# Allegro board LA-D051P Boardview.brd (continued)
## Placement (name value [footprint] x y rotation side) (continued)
PC111  4.7U_0603_6.3V6M  [C_0603]  65.27 16.56 90 bottom
PC112  680P_0603_50V7K  [C_0603]  68.26 18.09 180 bottom
PC113  1000P_0402_25V8J  [C_0402]  61.46 18.53 90 bottom
PC114  0.1U_0603_25V7K  [C_0603]  64.79 21.2 90 bottom
PC115  0.1U_0402_25V6  [C_0402]  58.22 25.32 90 top
PC116  2200P_0402_50V7K  [C_0402]  58.22 25.32 90 bottom
PC117  10U_0805_25V6K  [C_0805]  59.56 25.05 90 bottom
PC118  10U_0805_25V6K  [C_0805]  59.56 25.05 90 top
PC119  4.7U_0603_6.3V6M  [C_0603]  66.03 27.36 90 bottom
PC120  22U_0805_6.3V6M  [C_0805]  74.61 27.49 90 bottom
PC121  22U_0805_6.3V6M  [C_0805]  76.32 27.49 90 bottom
PC122  22U_0805_6.3V6M  [C_0805]  72.83 28.19 90 bottom
PC123  22U_0805_6.3V6M  [C_0805]  78.03 27.49 90 bottom
PC124  22U_0805_6.3V6M  [C_0805]  78.07 25.2 0 bottom
PC125  680P_0603_50V7K  [C_0603]  68.64 30.28 180 bottom
PC126  4.7U_0603_6.3V6M  [C_0603]  64.83 30.28 0 bottom
PC127  1000P_0402_25V8J  [C_0402]  61.72 30.28 90 bottom
PC128  4.7U_0402_6.3V6M  [C_0402]  61.78 30.2 90 top
PC200  0.1U_0603_25V7K  [C_0603]  89.78 14.91 180 bottom
PC201  2200P_0402_50V7K  [C_0402]  88.65 23.93 180 bottom
PC202  0.1U_0402_10V7K  [C_0402]  83.81 14.15 0 top
PC203  0.1U_0402_10V7K  [C_0402]  83.81 13.14 0 top
PC204  1U_0603_10V6K  [C_0603]  84.97 18.27 270 bottom
PC205  10U_0805_6.3V6K  [C_0805]  87.08 9.45 180 bottom
PC206  10U_0805_25V6K  [C_0805]  91.28 19.87 0 bottom
PC207  680P_0402_50V7K  [C_0402]  92.7 15.35 90 top
PC208  0.1U_0402_25V6  [C_0402]  88.65 23.04 180 bottom
PC209  1U_0603_10V6K  [C_0603]  81.31 16.89 90 bottom
PC210  0.033U_0402_16V7K  [C_0402]  84.26 10.42 270 bottom
PC211  10U_0805_6.3V6K  [C_0805]  87.08 7.67 180 bottom
PC212  10U_0805_25V6K  [C_0805]  88.73 21.71 180 bottom
PC213  .1U_0402_16V7K  [C_0402]  83.37 10.42 270 bottom
PC214  220P_0402_25V8J  [C_0402]  81.97 10.42 270 bottom
PC215  22U_0603_6.3V6M  [C_0603]  97.78 19.82 180 bottom
PC216  22U_0603_6.3V6M  [C_0603]  97.78 21.02 180 bottom
PC217  22U_0603_6.3V6M  [C_0603]  97.78 22.21 180 bottom
PC218  22U_0603_6.3V6M  [C_0603]  97.78 23.4 180 bottom
PC219  22U_0603_6.3V6M  [C_0603]  97.78 24.6 180 bottom
PC220  22U_0603_6.3V6M  [C_0603]  97.78 25.79 180 bottom
PC301  0.1U_0402_25V6  [C_0402]  174.24 50.93 270 bottom
PC302  680P_0603_50V7K  [C_0603]  174.24 46.66 90 bottom
PC303  2200P_0402_50V7K  [C_0402]  173.35 50.92 270 bottom
PC304  0.1U_0603_25V7K  [C_0603]  182.56 53.65 180 bottom
PC305  10U_0805_25V6K  [C_0805]  175.57 51.01 270 top
PC306  10U_0805_25V6K  [C_0805]  175.57 51.01 270 bottom
PC307  330P_0402_50V7K  [C_0402]  183.54 49.09 180 bottom
PC308  47U_0805_6.3V6M  [C_0805]  181.92 38.95 90 top
PC309  47U_0805_6.3V6M  [C_0805]  180.02 38.95 90 top
PC310  22U_0805_6.3VAM  [C_0805]  176.46 38.95 90 top
PC311  22U_0805_6.3VAM  [C_0805]  178.24 38.95 90 top
PC312  4.7U_0603_6.3V6K  [C_0603]  179.23 52.75 90 bottom
PC313  4.7U_0603_6.3V6K  [C_0603]  181.15 51.15 0 bottom
PC405  0.1U_0402_25V6  [C_0402]  182.23 46.41 0 bottom
PC501  22U_0603_6.3V6M  [C_0603]  82.79 31.75 180 bottom
PC502  22U_0603_6.3V6M  [C_0603]  87.5 26.78 270 bottom
PC503  68P_0402_50V8J  [C_0402]  81.79 26.06 270 bottom
PC504  22U_0603_6.3V6M  [C_0603]  82.8 30.53 180 bottom
PC505  0.1U_0402_16V7K  [C_0402]  82.67 28.26 270 bottom
PC506  680P_0402_50V7K  [C_0402]  87.69 28.69 270 bottom
PC601  680P_0402_50V7K  [C_0402]  87.81 118.15 90 top
PC602  0.1U_0402_25V6  [C_0402]  97.1 114.86 180 top
PC603  1U_0603_10V6K  [C_0603]  94.24 115.41 0 bottom
PC604  0.22U_0603_25V7K  [C_0603]  94.19 116.66 0 bottom
PC605  47P_0402_50V8J~D  [C_0402]  97.1 111.31 180 bottom
PC606  33U_25V_M  [C_VSS330M1ETR-0604]  73.37 117.21 0 bottom
PC608  10U_0805_25V6K  [C_0805]  146.55 118.32 270 top
PC611  0.22U_0603_16V7K  [C_0603]  148.9 115.24 270 top
PC612  10U_0805_25V6K  [C_0805]  146.55 118.32 270 bottom
PC613  330P_0402_50V8J  [C_0402]  91.03 111.79 270 top
PC614  2200P_0402_50V7K  [C_0402]  92.39 108.45 0 top
PC616  33P_0402_50V8J  [C_0402]  91.5 108.45 90 top
PC617  220P_0402_50V7K  [C_0402]  89.33 107.62 0 bottom
PC618  330P_0402_50V7K  [C_0402]  89.34 106.66 90 top
PC619  0.01U_0402_50V7K  [C_0402]  89.05 111.79 270 top
PC620  0.082U_0402_16V7K  [C_0402]  89.34 108.44 90 top
PC621  680P_0402_50V7K  [C_0402]  92.14 107.56 180 top
PC622  680P_0603_50V7K  [C_0603]  150.17 118.55 270 top
PC624  0.047U_0402_25V7K  [C_0402]  88.4 108.58 180 bottom
PC625  330P_0402_50V7K  [C_0402]  87.64 113.21 180 top
PC626  0.047U_0402_25V7K  [C_0402]  88.38 109.46 180 bottom
PC627  2200P_0402_50V7K  [C_0402]  84.69 108.6 0 bottom
PC628  10P_0402_50V8J  [C_0402]  86.87 118.96 180 bottom
PC629  2200P_0402_50V7K  [C_0402]  83.05 111.29 90 bottom
PC630  2200P_0402_50V7K  [C_0402]  85.67 120.39 180 bottom
PC631  1200P_0402_50V7K  [C_0402]  87.83 119.94 180 bottom
PC632  2200P_0402_25V7K  [C_0402]  92.77 117.71 90 bottom
PC633  6800P_0402_25V7K  [C_0402]  90.06 118.99 0 bottom
PC636  33P_0402_50V8J  [C_0402]  84.03 113.5 0 bottom
PC637  0.033U_0402_16V7K  [C_0402]  90.06 118.12 0 bottom
PC639  2200P_0402_25V7K  [C_0402]  84.06 115.52 0 bottom
PC640  2200P_0402_25V7K  [C_0402]  89.33 120.01 0 top
PC641  .1U_0402_16V7K  [C_0402]  87.48 107.69 0 top
PC642  0.047U_0402_25V7K  [C_0402]  84.89 117.71 90 bottom
PC643  330P_0402_50V7K  [C_0402]  88.05 116.23 270 top
PC644  .1U_0402_16V7K  [C_0402]  91.88 120.04 270 bottom
PC645  .1U_0402_16V7K  [C_0402]  82.24 113.63 270 top
PC646  0.047U_0402_25V7K  [C_0402]  84 117.71 90 bottom
PC647  680P_0402_50V7K  [C_0402]  84.08 112.13 180 top
PC649  0.01U_0402_50V7K  [C_0402]  89.4 116.27 270 top
PC650  0.082U_0402_16V7K  [C_0402]  91.13 118.1 180 top
PC651  330P_0402_50V7K  [C_0402]  84.13 113.52 90 top
PC652  330P_0402_50V7K  [C_0402]  91.1 120.01 0 top
PC653  0.082U_0402_16V7K  [C_0402]  83.99 116.83 0 bottom
PC654  0.01U_0402_50V7K  [C_0402]  87.64 114.1 180 top
PC655  0.22U_0603_16V7K  [C_0603]  99.27 116.16 0 bottom
PC656  10U_0805_25V6K  [C_0805]  103.06 118.17 0 bottom
PC657  10U_0805_25V6K  [C_0805]  103.05 118.16 0 top
PC658  10U_0805_25V6K  [C_0805]  103.05 116.45 0 top
PC659  0.1U_0402_25V6K~D  [C_0402]  100.91 118.55 180 bottom
PC660  2200P_0402_50V7K  [C_0402]  100.91 117.66 180 top
PC661  1U_0402_10V6K  [C_0402]  100.59 113.85 180 bottom
PC662  680P_0603_50V7K  [C_0603]  107.94 115.31 180 top
PC666  0.1U_0402_25V6K~D  [C_0402]  83.36 105.34 0 bottom
PC667  2200P_0402_50V7K  [C_0402]  83.36 106.23 0 top
PC671  0.22U_0603_16V7K  [C_0603]  79.24 102.42 0 bottom
PC672  10U_0805_25V6K  [C_0805]  83.11 104 0 top
PC673  10U_0805_25V6K  [C_0805]  83.11 104 0 bottom
PC677  1U_0402_10V6K  [C_0402]  80.32 100.14 270 bottom
PC678  680P_0603_50V7K  [C_0603]  93.34 103.94 180 top
PC679  1000P_0402_50V7K  [C_0402]  83.23 97.91 0 bottom
PC680  1000P_0402_50V7K  [C_0402]  100.91 118.55 180 top
PC685  1U_0402_10V6K  [C_0402]  150.48 114.99 0 bottom
PC686  10P_0402_25V8J  [C_0402]  100.91 117.66 180 bottom
PC688  10P_0402_25V8J  [C_0402]  83.36 105.34 0 top
PC705  2200P_0402_25V7K  [C_0402]  51.94 28.01 270 bottom
PC708  0.1U_0402_25V6  [C_0402]  42.47 14.14 90 bottom
PC711  0.01UF_0402_25V7K  [C_0402]  47.87 11.94 270 top
PC721  0.22U_0603_25V7K  [C_0603]  47.24 19.49 270 bottom
PC747  0.1U_0402_25V6  [C_0402]  49.9 12.77 270 bottom
PC748  2200P_0402_25V7K  [C_0402]  46.03 11.03 90 top
PC749  2200P_0402_25V7K  [C_0402]  45.08 11.94 270 top
PC750  0.22U_0603_25V7K  [C_0603]  51.3 13.96 180 bottom
PC751  560P_0402_50V7K  [C_0402]  40.57 9.45 0 bottom
PC752  0.015U_0402_25V7K  [C_0402]  40.51 7.66 90 bottom
PC753  10P_0402_50V8J  [C_0402]  40.5 12.31 0 bottom
PC757  1U_0603_25V6  [C_0603]  41.78 19.1 0 bottom
PC760  10U_0805_25V6K  [C_0805]  50.6 28.78 270 bottom
PC761  10U_0805_25V6K  [C_0805]  25.02 20.12 270 bottom
PC762  10U_0805_25V6K  [C_0805]  50.6 28.78 270 top
PC763  10U_0805_25V6K  [C_0805]  48.76 28.78 270 top
PC764  10U_0805_25V6K  [C_0805]  48.76 28.78 270 bottom
PC765  0.1U_0402_25V7K  [C_0402]  47.45 28.13 270 bottom
PC766  10U_0805_25V6K  [C_0805]  23.32 20.12 270 bottom
PC767  680P_0603_50V7K  [C_0603]  42.47 21.87 0 bottom
PC768  1U_0402_16V6K  [C_0402]  45 19.58 270 bottom
PC769  1U_0402_16V6K  [C_0402]  45.97 19.58 270 bottom
PC775  10U_0805_25V6K  [C_0805]  21.83 20.72 180 bottom
PC776  10U_0805_25V6K  [C_0805]  21.83 22.42 180 bottom
PC777  0.1U_0402_25V7K  [C_0402]  21.72 19.36 180 bottom
PC779  0.1U_0402_25V7K  [C_0402]  27.44 25.14 180 top
PC801  .1U_0402_16V7K  [C_0402]  73.65 48.3 90 top
PC802  2700P_0402_50V7K  [C_0402]  79.37 47.96 270 bottom
PC803  .1U_0603_25V7K  [C_0603]  80.22 42.37 180 bottom
PC804  1000P_0402_50V7K  [C_0402]  76.45 38.59 90 bottom
PC805  .1U_0402_16V7K  [C_0402]  78.23 39.5 270 bottom
PC806  0.1U_0603_25V7K  [C_0603]  70.79 41.32 270 bottom
PC807  1U_0603_10V6K  [C_0603]  71.75 43.43 180 bottom
PC808  0.1U_0603_25V7K  [C_0603]  70.99 46.08 270 bottom
PC813  0.1U_0402_25V6  [C_0402]  67.94 50.49 270 top
PC814  68P_0402_50V8J  [C_0402]  69.16 41.84 180 top
PC816  330U_D2_2V_Y  [C_X]  48.68 49.63 180 bottom
PC817  330U_D2_2V_Y  [C_X]  48.68 44.59 180 bottom
PC819  680P_0402_50V7K  [C_0402]  62.53 49.52 0 top
PC820  680P_0402_50V7K  [C_0402]  62.46 43.17 0 top
PC821  4.7U_0603_6.3V6M  [C_0603]  66.37 74.22 270 top
PC822  4.7U_0603_6.3V6M  [C_0603]  66.37 76.66 270 top
PC823  4.7U_0603_6.3V6M  [C_0603]  68.33 76.73 270 top
PC824  4.7U_0603_6.3V6M  [C_0603]  69.79 77.17 90 top
PC825  4.7U_0603_6.3V6M  [C_0603]  51.43 56.57 90 bottom
PC826  4.7U_0603_6.3V6M  [C_0603]  54.6 56.57 90 bottom
PC827  4.7U_0603_6.3V6M  [C_0603]  53.02 56.57 90 bottom
PC828  4.7U_0603_6.3V6M  [C_0603]  55.87 56.57 90 top
PC829  4.7U_0603_6.3V6M  [C_0603]  57.14 56.57 90 top
PC830  4.7U_0603_6.3V6M  [C_0603]  57.14 56.57 90 bottom
PC835  1U_0402_16V6K  [C_0402]  64.4 75.66 270 top
PC840  47U_0805_6.3V6M  [C_0805]  60.45 56.42 90 top
PC841  1U_0402_16V6K  [C_0402]  64.4 76.52 90 top
PC842  4.7U_0603_6.3V6M  [C_0603]  55.87 56.57 90 bottom
PC843  4.7U_0603_6.3V6M  [C_0603]  68.33 74.31 270 top
PC844  1U_0402_16V6K  [C_0402]  63.63 78.92 135 top
PC845  4.7U_0603_6.3V6M  [C_0603]  68.33 71.9 270 top
PC846  4.7U_0603_6.3V6M  [C_0603]  66.49 71.84 270 top
PC847  1U_0402_16V6K  [C_0402]  60.89 72.39 270 top
PC848  4.7U_0603_6.3V6M  [C_0603]  64.46 71.9 270 top
PC849  22U_0805_6.3V6M  [C_0805]  58.67 56.42 90 top
PC850  4.7U_0603_6.3V6M  [C_0603]  62.49 71.9 270 top
PC858  0.1U_0402_25V6  [C_0402]  64.46 73.82 270 top
PC859  0.1U_0402_25V6  [C_0402]  62.3 73.88 270 top
PC860  0.1U_0402_25V6  [C_0402]  62.3 75.71 270 top
PC861  0.1U_0402_25V6  [C_0402]  62.3 77.46 270 top
PC1001  22U_0603_6.3V6M  [C_0603]  143.82 115.69 90 top
PC1002  22U_0603_6.3V6M  [C_0603]  141.73 115.69 90 bottom
PC1003  22U_0603_6.3V6M  [C_0603]  127.92 91.63 0 top
PC1004  22U_0603_6.3V6M  [C_0603]  129.34 90.41 180 top
PC1005  22U_0603_6.3V6M  [C_0603]  127.97 89.17 0 top
PC1006  22U_0603_6.3V6M  [C_0603]  125.28 91.62 0 top
PC1007  22U_0603_6.3V6M  [C_0603]  139.57 115.69 90 bottom
PC1008  22U_0603_6.3V6M  [C_0603]  140.39 112.89 90 bottom
PC1009  22U_0603_6.3V6M  [C_0603]  127.18 115.43 90 bottom
PC1010  22U_0603_6.3V6M  [C_0603]  143 112.89 90 bottom
PC1011  22U_0603_6.3V6M  [C_0603]  143 112.89 90 top
PC1012  22U_0603_6.3V6M  [C_0603]  127.18 115.43 90 top
PC1013  22U_0603_6.3V6M  [C_0603]  140.39 112.89 90 top
PC1014  22U_0603_6.3V6M  [C_0603]  108.51 95.56 270 top
PC1015  22U_0603_6.3V6M  [C_0603]  109.78 95.56 270 top
PC1016  22U_0603_6.3V6M  [C_0603]  111.99 101.31 180 top
PC1017  22U_0603_6.3V6M  [C_0603]  112.13 97.34 180 top
PC1018  22U_0603_6.3V6M  [C_0603]  96.39 91.37 90 bottom
PC1019  22U_0603_6.3V6M  [C_0603]  102.42 95.56 270 bottom
PC1020  22U_0603_6.3V6M  [C_0603]  103.63 95.56 270 bottom
PC1021  22U_0603_6.3V6M  [C_0603]  100.01 91.37 90 bottom
PC1022  22U_0603_6.3V6M  [C_0603]  97.59 91.37 90 bottom
PC1023  22U_0603_6.3V6M  [C_0603]  97.59 95.56 270 bottom
PC1024  22U_0603_6.3V6M  [C_0603]  98.8 95.56 270 bottom
PC1025  22U_0603_6.3V6M  [C_0603]  108.32 97.34 0 top
PC1026  22U_0603_6.3V6M  [C_0603]  107.31 97.34 180 top
PC1027  22U_0603_6.3V6M  [C_0603]  106.1 91.37 90 top
PC1028  22U_0603_6.3V6M  [C_0603]  106.04 95.56 270 top
PC1029  22U_0603_6.3V6M  [C_0603]  107.31 95.56 270 top
PC1030  1U_0201_6.3V6M  [C_0201]  130.24 97.87 90 top
PC1033  1U_0201_6.3V6M  [C_0201]  127.22 102.29 180 top
PC1034  1U_0201_6.3V6M  [C_0201]  132.07 97.84 90 top
PC1036  1U_0201_6.3V6M  [C_0201]  131.15 99.43 0 top
PC1037  1U_0201_6.3V6M  [C_0201]  133.03 88.41 90 top
PC1038  1U_0201_6.3V6M  [C_0201]  127.16 97.72 180 top
PC1039  1U_0201_6.3V6M  [C_0201]  131.92 102.23 180 top
PC1040  1U_0201_6.3V6M  [C_0201]  120.72 97.66 90 top
PC1041  1U_0201_6.3V6M  [C_0201]  111.84 99.91 180 top
PC1042  1U_0201_6.3V6M  [C_0201]  114.27 94.08 90 top
PC1043  1U_0201_6.3V6M  [C_0201]  113.22 93.95 90 top
PC1044  1U_0201_6.3V6M  [C_0201]  115.74 96.02 90 top
PC1045  1U_0201_6.3V6M  [C_0201]  113.13 90.92 0 top
PC1046  1U_0201_6.3V6M  [C_0201]  112.44 91.74 270 top
PC1047  1U_0201_6.3V6M  [C_0201]  113.2 92.76 90 top
PC1048  1U_0201_6.3V6M  [C_0201]  116.83 91.85 270 top
PC1049  1U_0201_6.3V6M  [C_0201]  116.91 96.11 90 top
PC1050  1U_0201_6.3V6M  [C_0201]  130.08 102.23 180 top
PC1052  1U_0201_6.3V6M  [C_0201]  128.91 97.95 0 top
PC1053  1U_0201_6.3V6M  [C_0201]  131.02 88.32 0 top
PC1055  1U_0201_6.3V6M  [C_0201]  111.17 93.62 270 top
PC1056  1U_0201_6.3V6M  [C_0201]  116.26 91.85 270 top
PC1057  22U_0603_6.3V6M  [C_0603]  137.41 92.83 180 top
PC1058  22U_0603_6.3V6M  [C_0603]  137.41 94.1 180 top
PC1059  22U_0603_6.3V6M  [C_0603]  137.41 95.37 180 top
PC1060  22U_0603_6.3V6M  [C_0603]  137.41 96.64 180 top
PC1061  22U_0603_6.3V6M  [C_0603]  130.87 89.21 0 top
PC1062  220U 2V Y D2  [C_D2]  135.72 115.18 180 top
PC1063  330U_D2_2V_Y  [C_D2]  127.53 94.94 0 top
PC1064  22U_0603_6.3V6M  [C_0603]  131.76 90.42 180 top
PC1065  22U_0603_6.3V6M  [C_0603]  134.11 90.42 180 top
PC1066  22U_0603_6.3V6M  [C_0603]  132.71 91.62 0 top
PC1069  22U_0603_6.3V6M  [C_0603]  125.28 89.21 0 top
PC1070  22U_0603_6.3V6M  [C_0603]  126.68 90.42 180 top
PC1071  22U_0603_6.3V6M  [C_0603]  139.57 115.69 90 top
PC1072  22U_0603_6.3V6M  [C_0603]  143.82 115.69 90 bottom
PC1073  22U_0603_6.3V6M  [C_0603]  124.01 90.86 180 top
PC1074  22U_0603_6.3V6M  [C_0603]  124.01 89.59 180 top
PC1075  22U_0603_6.3V6M  [C_0603]  126.49 112.77 90 top
PC1076  22U_0603_6.3V6M  [C_0603]  125.6 115.43 90 top
PC1077  22U_0603_6.3V6M  [C_0603]  124.71 112.77 90 bottom
PC1078  22U_0603_6.3V6M  [C_0603]  125.6 115.43 90 bottom
PC1079  22U_0603_6.3V6M  [C_0603]  123.88 115.43 90 bottom
PC1080  22U_0603_6.3V6M  [C_0603]  126.49 112.77 90 bottom
PC1081  22U_0603_6.3V6M  [C_0603]  124.71 112.77 90 top
PC1082  22U_0603_6.3V6M  [C_0603]  123.88 115.43 90 top
PC1083  1U_0201_6.3V6M  [C_0201]  128.33 97.93 90 top
PC1084  1U_0201_6.3V6M  [C_0201]  127.16 98.29 180 top
PC1085  1U_0201_6.3V6M  [C_0201]  130.08 101.65 180 top
PC1086  1U_0201_6.3V6M  [C_0201]  130.51 99.43 180 top
PC1087  1U_0201_6.3V6M  [C_0201]  130.69 101.05 0 top
PC1088  1U_0201_6.3V6M  [C_0201]  132.84 99.42 0 top
PC1089  1U_0201_6.3V6M  [C_0201]  132.67 98.31 0 top
PC1090  1U_0201_6.3V6M  [C_0201]  130.81 98.31 0 top
PC1092  1U_0201_6.3V6M  [C_0201]  134.33 99.47 45 top
PC1093  1U_0201_6.3V6M  [C_0201]  134.84 99.14 45 top
PC1094  1U_0201_6.3V6M  [C_0201]  130.69 100.42 0 top
PC1095  1U_0201_6.3V6M  [C_0201]  134.42 98.28 0 top
PC1096  1U_0201_6.3V6M  [C_0201]  133.83 102.42 180 top
PC1097  1U_0201_6.3V6M  [C_0201]  132.84 86.63 90 top
PC1098  1U_0201_6.3V6M  [C_0201]  124.11 88.45 180 top
PC1099  1U_0201_6.3V6M  [C_0201]  123.9 91.78 180 top
PC1125  1U_0201_6.3V6M  [C_0201]  132.25 86.63 90 top
PC1126  1U_0201_6.3V6M  [C_0201]  131.61 86.63 90 top
PC1127  220U 2V Y D2  [C_D2]  135.72 115.18 180 bottom
PC1129  22U_0603_6.3V6M  [C_0603]  122.8 94.1 270 top
PC1130  22U_0603_6.3V6M  [C_0603]  122.8 96.51 270 top
PC1131  22U_0603_6.3V6M  [C_0603]  120.22 96.22 0 top
PC1132  22U_0603_6.3V6M  [C_0603]  124.33 100.89 0 top
PC1133  22U_0603_6.3V6M  [C_0603]  121.98 100.89 0 top
PC1134  22U_0603_6.3V6M  [C_0603]  121.64 94.93 180 top
PC1135  22U_0603_6.3V6M  [C_0603]  120.26 93.64 0 top
PC1136  22U_0603_6.3V6M  [C_0603]  121.64 92.41 180 top
PC1137  22U_0603_6.3V6M  [C_0603]  120.25 91.15 0 top
PC1138  22U_0603_6.3V6M  [C_0603]  118.61 94.42 90 top
PC1139  22U_0603_6.3V6M  [C_0603]  164.71 116.76 90 bottom
PC1140  22U_0603_6.3V6M  [C_0603]  165.73 113.66 90 bottom
PC1141  22U_0603_6.3V6M  [C_0603]  160.58 113.66 90 bottom
PC1142  22U_0603_6.3V6M  [C_0603]  161.35 116.76 90 bottom
PC1143  22U_0603_6.3V6M  [C_0603]  163.04 116.78 90 bottom
PC1144  22U_0603_6.3V6M  [C_0603]  164.01 113.66 90 bottom
PC1145  22U_0603_6.3V6M  [C_0603]  162.3 113.66 90 bottom
PC1146  22U_0603_6.3V6M  [C_0603]  137.9 88.86 0 top
PC1147  1U_0201_6.3V6M  [C_0201]  138.56 87.97 0 top
PC1148  1U_0201_6.3V6M  [C_0201]  138.19 95.62 0 top
PC1149  1U_0201_6.3V6M  [C_0201]  138.19 96.19 0 top
PC1150  1U_0201_6.3V6M  [C_0201]  138.19 96.77 0 top
PC1151  1U_0201_6.3V6M  [C_0201]  135.65 97.94 90 top
PC1152  1U_0201_6.3V6M  [C_0201]  136.3 99.52 0 top
PC1153  1U_0201_6.3V6M  [C_0201]  136.42 98.1 0 top
PC1154  22U_0603_6.3V6M  [C_0603]  100.01 97.08 90 bottom
PC1155  22U_0603_6.3V6M  [C_0603]  102.42 97.08 90 bottom
PC1156  22U_0603_6.3V6M  [C_0603]  101.21 97.08 90 bottom
PC1158  22U_0603_6.3V6M  [C_0603]  98.8 91.37 90 bottom
PC1159  22U_0603_6.3V6M  [C_0603]  101.21 95.56 270 bottom
PC1161  22U_0603_6.3V6M  [C_0603]  107.31 91.37 90 top
PC1162  22U_0603_6.3V6M  [C_0603]  108.51 91.37 90 top
PC1163  22U_0603_6.3V6M  [C_0603]  109.78 91.37 90 top
PC1164  1U_0201_6.3V6M  [C_0201]  130.98 86.63 90 top
PC1173  22U_0603_6.3V6M  [C_0603]  130.34 91.63 0 top
PC1174  22U_0603_6.3V6M  [C_0603]  141.73 115.69 90 top
PC1175  22U_0603_6.3V6M  [C_0603]  124.33 98.04 0 top
PC1176  22U_0603_6.3V6M  [C_0603]  124.07 96.51 270 top
PC1177  22U_0603_6.3V6M  [C_0603]  124.07 94.1 270 top
PC1178  22U_0603_6.3V6M  [C_0603]  114.62 92.45 270 top
PC1179  22U_0603_6.3V6M  [C_0603]  102.42 91.37 90 bottom
PC1180  22U_0603_6.3V6M  [C_0603]  101.21 91.37 90 bottom
PC1181  22U_0603_6.3V6M  [C_0603]  119.08 97.98 180 top
PC1182  22U_0603_6.3V6M  [C_0603]  124.33 102.1 0 top
PC1183  22U_0603_6.3V6M  [C_0603]  100.01 95.56 270 bottom
PC1184  22U_0603_6.3V6M  [C_0603]  121.98 102.1 0 top
PC1221  22U_0603_6.3V6M  [C_0603]  103.63 91.37 90 bottom
PC1222  22U_0603_6.3V6M  [C_0603]  121.02 102.1 180 top
PC1223  22U_0603_6.3V6M  [C_0603]  121.02 100.89 180 top
PC1224  22U_0603_6.3V6M  [C_0603]  118.61 93.34 270 top
PC2118  10U_0805_25V6K  [C_0805]  68 50.88 270 bottom
PC2119  10U_0805_25V6K  [C_0805]  69.72 50.88 270 bottom
PC2120  10U_0805_25V6K  [C_0805]  69.34 39.97 90 bottom
PC2121  10U_0805_25V6K  [C_0805]  67.62 39.97 90 bottom
PD2  -  [TVNST52302AB0_SOT523-3]  18.98 23.17 90 bottom
PD3  -  [TVNST52302AB0_SOT523-3]  19 17.56 90 bottom
PD101  -  [TVNST52302AB0_SOT523-3]  66.29 30.6 270 top
PD102  -  [SDMK0340L-7-F_SOD323-2]  58.04 30.22 0 top
PD704  -  [SDMK0340L-7-F_SOD323-2]  39.3 18.22 180 bottom
PD705  -  [SDMK0340L-7-F_SOD323-2]  39.3 16.44 180 bottom
PD706  -  [SDMK0340L-7-F_SOD323-2]  31.51 37.92 270 top
PH601  470K_0402_5%_ TSM0B474J4702RE  [R_0402]  85.9 97.84 0 bottom
PH602  10K_0402_5%_ERTJ0ER103J  [R_0402]  90.53 96.64 0 bottom
PH603  470K_0402_5%_ TSM0B474J4702RE  [R_0402]  106.22 112.13 0 bottom
PH604  10KB_0402_5%_ERTJ0ER103J  [R_0402]  156.86 121.34 0 bottom
PH605  10KB_0402_5%_ERTJ0ER103J  [R_0402]  117.5 119.79 180 bottom
PJP1  JUMP_43X79  [JUMP_43X79-NPM]  19.61 108.44 180 top
PJP2  JUMP_43X79  [JUMP_43X79-NPM]  26.32 110.01 90 top
PJP3  JUMP_43X79  [JUMP_43X79-NPM]  19.83 27.28 0 bottom
PJP102  -  [JUMP_43X118]  77.72 11.8 0 bottom
PJP103  -  [JUMP_43X118]  78.06 22.92 270 bottom
PJP105  -  [JUMP_43X79]  55.49 17.43 270 bottom
PJP106  -  [JUMP_43X79]  57.97 21.01 90 bottom
PJP200  -  [JUMP_43X118]  99.76 21.61 0 bottom
PJP202  -  [JUMP_43X118]  99.76 26.89 0 bottom
PJP203  -  [JUMP_43X79]  89.91 8.97 180 bottom
PJP206  -  [JUMP_43X79]  91.32 23.87 90 bottom
PJP301  -  [JUMP_43X79]  171.8 51.55 180 bottom
PJP302  -  [JUMP_43X118]  172.9 39.32 90 top
PJP501  -  [JUMP_43X79]  84.13 21.54 90 bottom
PJP502  -  [JUMP_43X79]  85.27 32.95 90 bottom
PJP601  PAD-OPEN 4x4m  [JUMP_43X118]  46.56 117.18 180 bottom
PJP602  PAD-OPEN 4x4m  [JUMP_43X118]  81.19 105.85 180 bottom
PJP603  PAD-OPEN1x1m  [JUMP_43X39]  145.87 120.01 180 bottom
PJP701  -  [JUMP_43X118]  44.38 34.28 90 bottom
PJP801  -  [JUMP_43X79]  69.51 38.7 90 top
PJPDC  ACES_50299-00501-003  [ACES_50299-00501-003_5P]  21.5 112.3 90 top
PL1  FBMJ4516HS720NT_2P  [MURAT_BLM41PG600SN1L_2P]  17.14 108.26 0 top
PL2  BLM15AG102SN1D_2P  [MURAT_BLM15AG102SN1D_2P]  20.38 105.23 90 top
PL3  FBMJ4516HS720NT_2P  [MURAT_BLM41PG600SN1L_2P]  22.28 27.3 180 bottom
PL4  FBMJ4516HS720NT_2P  [MURAT_BLM41PG600SN1L_2P]  26.28 112.65 270 top
PL100  1.5UH_PCMC063T-1R5MN_9A_20%  [L_7X7X3_M_2P]  66.35 11.69 0 bottom
PL101  2.2UH +-20% 7.8A 7X7X3 MOLDING  [L_7X7X3_M_2P]  67.3 23.14 0 bottom
PL102  FBMJ4516HS720NT_2P  [TAIYO_FBMJ4516HS720NT_2P-NPM]  55.49 18.86 270 bottom
PL103  FBMJ4516HS720NT_2P  [TAIYO_FBMJ4516HS720NT_2P-NPM]  57.97 19.55 90 bottom
PL200  1UH_11A_20%_7X7X3_M  [L_7X7X3_M_2P]  99.35 15.23 180 bottom
PL301  0.68UH +-20% 7.9A  [L_5X5X3_M_2P]  178.87 45.6 270 bottom
PL501  1UH_PHT25201B-1R0MS_2.45A_20%  [CYNTE_PHT25201B-1R0MS_2P]  85.93 29.65 180 bottom
PL601  0.68UH +-20% 7.9A  [L_5X5X3_M_2P]  154.36 117.72 0 bottom
PL602  FBMA-L11-453215800LMA90T_2P  [KC_FBMA-L11-4532158_2P-NPM]  47.93 117.13 180 bottom
PL603  .15UH +-20% 29A 7X7X4 MOLDING  [L_7X7X3_M_2P]  114.23 115.12 0 bottom
PL605  .15UH +-20% 29A 7X7X4 MOLDING  [L_7X7X3_M_2P]  89.08 101.15 0 bottom
PL700  4.7UH_5.5A_20%_7X7X3_M  [L_7X7X3_M_2P]  39.59 27.04 180 bottom
PL704  1UH_PCMB053T-1R0MS_7A_20%  [L_5X5X3_M_2P-NPM]  44.38 32.65 90 bottom
PL801  HCB2012KF-121T50_0805  [TAI-T_HCB2012KF-121T50_2P-NPM]  69.45 36.69 180 bottom
PL802  0.36UH_PDME064T-R36MS1R405_24A_20%  [L_7X7X3_M_2P]  59.18 51.68 180 bottom
PL803  0.36UH_PDME064T-R36MS1R405_24A_20%  [L_7X7X3_M_2P]  59.18 43.49 180 bottom
PQ1  L2N7002DW1T1G_SC88-6  [2N7002DW-T-R7_SOT363-6]  34.83 105.32 90 top
PQ2  L2N7002DW1T1G_SC88-6  [2N7002DW-T-R7_SOT363-6]  34.83 113.32 90 top
PQ3  L2N7002DW1T1G_SC88-6  [2N7002DW-T-R7_SOT363-6]  22.66 17.01 270 bottom
PQ5  MMST3904-7-F_SOT323  [RHU002N06_SOT323-3]  22.41 101.31 180 top
PQ6  FDV301N_G 1N SOT23-3  [FDV301N_NL_SOT23-3]  22.92 105.49 180 top
PQ201  -  [AON7934_DFN3X3A8-10]  90.02 20.02 270 bottom
PQ501  AON7934_DFN3X3A-8-10  [AON7934_DFN3X3A8-10]  148.5 119.69 0 bottom
PQ704  AON7408L_DFN8-5  [SIS412DN-T1-GE3_POWERPAK8-5]  43.45 27.96 90 bottom
PQ707  L2N7002DW1T1G_SC88-6  [2N7002DW-T-R7_SOT363-6]  24.43 36.97 0 top
PQ708  AON7506_DFN33-8-5  [SIS412DN-T1-GE3_POWERPAK8-5]  45.88 23.23 180 bottom
PQ709  L2N7002DW1T1G_SC88-6  [2N7002DW-T-R7_SOT363-6]  28.72 36.07 0 top
PQ710  -  [LMUN5113T1G_SOT323-3]  38.65 14.15 90 top
PQ711  -  [LTC015EUBFS8TL_UMT3F]  35.13 14.18 270 top
PQ717  MDU1512RH_POWERDFN56-8-5  [SIR472DP-T1-GE3_POWERPAK8-5]  30.28 25.2 180 bottom
PQ718  MDU1512RH_POWERDFN56-8-5  [SIR472DP-T1-GE3_POWERPAK8-5]  28.01 34.29 90 bottom
PQ740  AON7426_DFN3X3EP8-5  [SIS412DN-T1-GE3_POWERPAK8-5]  24.71 38.01 270 bottom
PQ800  -  [AON6992_DFN5X6D-8-7]  62.22 52.86 0 bottom
PQ801  -  [AON6992_DFN5X6D-8-7]  65.67 38.51 180 bottom
PR2  10K_0402_1%  [R_0402]  36.25 107.26 270 top
PR3  2.2K_0402_5%  [R_0402]  25.33 101.1 270 top
PR4  33_0402_5%  [R_0402]  25.33 103.38 270 top
PR5  3.3K_1206_5%  [R_1206]  30.22 110.54 0 top
PR6  100K_0402_1%  [R_0402]  20.58 101.27 180 top
PR7  1M_0402_1%  [R_0402]  31.12 108.64 180 top
PR8  10K_0402_1%  [R_0402]  24.31 100.18 90 top
PR9  15K_0402_1%  [R_0402]  19.67 100 0 top
PR10  1M_0402_1%  [R_0402]  30.14 105.59 0 top
PR15  200_0402_5%  [R_0402]  17.55 19.12 0 bottom
PR16  10K_0402_1%  [R_0402]  17.54 20.1 0 bottom
PR18  100_0402_5%  [R_0402]  17.55 24.72 0 bottom
PR20  100_0402_5%  [R_0402]  17.51 21.71 0 bottom
PR28  10K_0402_1%  [R_0402]  37.39 113.77 90 top
PR29  100K_0402_1%  [R_0402]  36.56 112.83 0 top
PR31  1M_0402_1%  [R_0402]  31.12 112.45 180 top
PR32  100K_0402_1%  [R_0402]  19.23 16.01 270 bottom
PR33  1M_0402_1%  [R_0402]  30.21 113.47 0 top
PR37  10K_0402_1%  [R_0402]  18.34 16.06 180 bottom
PR100  0_0603_5%  [R0603_0OHM]  62.63 10.79 270 bottom
PR102  499K_0402_1%  [R_0402]  59.87 17.38 90 top
PR103  499K_0402_1%  [R_0402]  61.19 16.69 0 top
PR106  4.7_1206_5%  [R_1206]  66.99 16.44 0 bottom
PR107  10K_0402_5%  [R_0402]  64.13 18.53 90 bottom
PR108  1K_0402_5%  [R_0402]  62.35 19.42 0 bottom
PR109  150K_0402_1%  [R_0402]  63.24 18.53 180 bottom
PR110  150K_0402_1%  [R_0402]  60.57 18.53 90 bottom
PR111  0_0603_5%  [R0603_0OHM]  63.58 22.6 270 bottom
PR112  4.7_1206_5%  [R_1206]  67.49 28.63 0 bottom
PR113  10K_0402_5%  [R_0402]  59.1 28.25 0 top
PR114  2.2K_0402_5%  [R_0402]  63.68 30.2 90 top
PR115  150K_0402_1%  [R_0402]  63.49 30.28 180 bottom
PR116  0_0402_5%  [R0402_0OHM]  57.89 31.55 0 top
PR117  1K_0402_5%  [R_0402]  62.6 31.17 0 bottom
PR118  150K_0402_1%  [R_0402]  60.83 30.28 90 bottom
PR120  0_0402_5%  [R0402_0OHM]  62.79 30.2 90 top
PR121  0_0402_5%  [R0402_0OHM]  59.68 18.52 90 bottom
PR200  0_0603_5%  [R0603_0OHM]  89.78 13.26 180 bottom
PR201  0_0402_5%  [R0402_0OHM]  81.07 13.14 0 bottom
PR202  0_0402_5%  [R0402_0OHM]  81.07 12.25 0 bottom
PR203  4.7_1206_5%  [R_1206]  93.91 15.93 0 top
PR204  68.1K_0402_1%  [R_0402]  81.98 11.36 180 bottom
PR205  10.2K_0402_1%  [R_0402]  84.41 15.05 0 top
PR206  5.1_0603_5%  [R_0603]  82.54 18.28 270 bottom
PR207  54.9K_0402_1%  [R_0402]  81.08 10.42 270 bottom
PR208  453K_0402_1%  [R_0402]  81.07 14.02 0 bottom
PR209  10K_0402_1%  [R_0402]  81.07 14.98 0 bottom
PR210  2.2_0603_5%  [R_0603]  83.75 16.88 90 bottom
PR302  1M_0402_1%  [R_0402]  182.23 45.52 0 bottom
PR303  4.7_1206_5%  [R_1206]  174.3 42.85 90 bottom
PR304  0_0603_5%  [R0603_0OHM]  181.16 52.44 0 bottom
PR306  6.65K_0402_1%  [R_0402]  183.54 49.98 180 bottom
PR307  0_0402_5%  [R_0402]  183.14 48.19 180 bottom
PR308  1K_0402_5%  [R_0402]  181.77 49.11 90 bottom
PR310  0_0402_5%  [R_0402]  182.23 47.3 0 bottom
PR311  10K_0402_1%  [R_0402]  183.56 50.88 90 bottom
PR312  0_0402_5%  [R0402_0OHM]  182.23 43.74 0 bottom
PR313  0_0402_5%  [R_0402]  183.14 44.63 180 bottom
PR314  10K_0402_5%  [R_0402]  183.14 42.85 180 bottom
PR315  0_0402_5%  [R_0402]  182.37 41.05 90 bottom
PR501  20K_0402_1%  [R_0402]  82.68 26.06 270 bottom
PR502  4.7_0603_5%  [R_0603]  87.81 31.04 270 bottom
PR504  0_0402_5%  [R_0402]  81.77 29.14 0 bottom
PR505  1M_0402_1%  [R_0402]  81.78 28.26 270 bottom
PR506  10K_0402_1%  [R_0402]  82.7 24.27 180 bottom
PR507  0_0402_5%  [R0402_0OHM]  80.89 27.35 90 bottom
PR601  45.3_0402_1%  [R_0402]  97.1 112.2 180 top
PR602  0_0402_5%  [R0402_0OHM]  94.32 115.47 0 top
PR603  0_0402_5%  [R0402_0OHM]  94.32 116.67 0 top
PR604  75_0402_1%  [R_0402]  97.1 113.08 180 top
PR605  100_0402_1%  [R_0402]  97.1 113.97 180 top
PR606  0_0402_5%  [R0402_0OHM]  97.12 112.21 180 bottom
PR607  0_0402_5%  [R0402_0OHM]  97.12 113.08 180 bottom
PR608  78.7K_0402_1%  [R_0402]  92.08 114.48 180 top
PR609  0_0402_5%  [R0402_0OHM]  97.12 113.96 180 bottom
PR610  10K_0402_1%  [R_0402]  91.26 108.54 90 bottom
PR611  48.7K_0402_1%  [R_0402]  92.08 115.37 180 top
PR612  1.91K_0402_1%  [R_0402]  94.9 110.43 180 bottom
PR613  86.6K_0402_1%  [R_0402]  92.13 108.54 90 bottom
PR616  0_0402_5%  [R0402_0OHM]  94.89 109.51 180 bottom
PR617  3.6K_0402_1%  [R_0402]  93.27 109.34 180 top
PR618  49.9_0402_1%  [R_0402]  94.9 112.22 180 bottom
PR619  0_0603_5%  [R0603_0OHM]  145.85 115.24 0 top
PR620  0_0402_5%  [R0402_0OHM]  93.02 108.53 90 bottom
PR621  1K_0402_1%  [R_0402]  90.23 108.56 90 bottom
PR622  1.96K_0402_1%  [R_0402]  89.32 108.54 90 bottom
PR623  2K_0402_1%  [R_0402]  90.61 108.44 90 top
PR624  3.65K_0603_1%  [R_0603]  97.78 118.55 180 bottom
PR625  0_0402_5%  [R0402_0OHM]  94.9 113.08 180 bottom
PR626  10_0402_1%  [R_0402]  94.9 113.97 180 bottom
PR627  4.7_1206_5%  [R_1206]  154.23 118.1 180 top
PR628  4.42K_0402_1%  [R_0402]  88.4 108.58 180 top
PR629  84.5K_0402_1%  [R_0402]  87.64 112.26 180 top
PR630  4.02K_0402_1%  [R_0402]  87.8 118.13 90 bottom
PR631  27.4K_0402_1%  [R_0402]  91.94 111.76 270 top
PR632  1K_0402_1%  [R_0402]  85.59 107.73 180 bottom
PR633  11K_0402_1%  [R_0402]  88.4 107.69 180 bottom
PR635  10K_0402_1%  [R_0402]  84.89 110.38 90 bottom
PR636  1.24K_0402_1%  [R_0402]  93.66 117.71 90 bottom
PR637  20M_0402_5%  [R_0402]  87.52 110.43 90 top
PR638  274_0402_1%  [R_0402]  86.48 107.69 90 bottom
PR639  3K_0402_1%  [R_0402]  83.97 112.16 0 bottom
PR640  255_0402_1%  [R_0402]  86.89 118.1 180 bottom
PR641  1K_0402_1%  [R_0402]  92.75 119.5 0 bottom
PR642  2.61K_0402_1%  [R_0402]  95.43 119.13 270 bottom
PR643  11K_0402_1%  [R_0402]  94.54 118.22 90 bottom
PR644  1K_0402_1%  [R_0402]  84.64 119.5 180 bottom
PR645  316_0402_1%  [R_0402]  84.97 114.61 180 bottom
PR646  316_0402_1%  [R_0402]  89.21 118.15 90 bottom
PR647  27.4K_0402_1%  [R_0402]  84 111.31 270 bottom
PR648  1.37K_0402_1%  [R_0402]  83.17 115.53 270 bottom
PR649  1.69K_0402_1%  [R_0402]  90.21 118.99 0 top
PR650  2K_0402_1%  [R_0402]  83.18 114.43 270 top
PR651  140K_0402_1%  [R_0402]  87.18 116.23 270 top
PR652  2K_0402_1%  [R_0402]  89.27 118.09 90 top
PR654  20M_0402_5%  [R_0402]  90.29 116.27 270 top
PR655  20M_0402_5%  [R_0402]  86.29 116.21 270 top
PR656  11K_0402_1%  [R_0402]  83.05 117.71 90 bottom
PR657  4.42K_0402_1%  [R_0402]  82.1 117.71 90 bottom
PR658  0_0402_5%  [R_0402]  103.45 111.88 180 bottom
PR659  0_0402_5%  [R0402_0OHM]  100.59 112.96 180 bottom
PR660  0_0603_5%  [R0603_0OHM]  99.26 114.95 0 bottom
PR661  3.65K_0603_1%  [R_0603]  82.04 115.12 90 bottom
PR662  0_0402_5%  [R0402_0OHM]  79.43 100.14 270 bottom
PR663  4.7_1206_5%  [R_1206]  111.8 115.32 180 top
PR664  0_0402_5%  [R0402_0OHM]  100.76 111.88 0 bottom
PR671  0_0402_5%  [R0402_0OHM]  80.33 98.35 180 bottom
PR672  0_0603_5%  [R0603_0OHM]  79.24 101.21 0 bottom
PR673  0_0402_5%  [R0402_0OHM]  81.34 112.69 90 top
PR674  3.65K_0603_1%  [R_0603]  89.02 106.04 180 bottom
PR675  0_0402_5%  [R0402_0OHM]  88.58 105.97 135 top
PR676  4.7_1206_5%  [R_1206]  91.5 102.3 0 top
PR678  100_0402_1%  [R_0402]  94.9 111.33 180 bottom
PR679  0_0402_5%  [R0402_0OHM]  150.48 114.04 0 bottom
PR682  0_0402_5%  [R_0402]  77.78 98.1 315 bottom
PR683  0_0402_5%  [R0402_0OHM]  79.86 97.34 0 bottom
PR703  0.01_1206_1%  [R_1206_4P]  34.92 34.92 0 bottom
PR720  3.3K_1206_5%  [R_1206]  22.66 35.68 90 top
PR727  10.5K_0402_1%  [R_0402]  42.54 9.47 270 bottom
PR729  392K_0402_1%  [R_0402]  48.76 8.55 90 bottom
PR731  158K_0402_1%  [R_0402]  46.92 11.03 90 top
PR732  49.9K_0402_1%  [R_0402]  49.65 8.55 90 bottom
PR737  3M_0402_5%  [R_0402]  28.43 34.73 0 top
PR738  1M_0402_1%  [R_0402]  29.33 33.85 270 top
PR739  1M_0402_1%  [R_0402]  30.09 39.6 90 top
PR740  2_0402_5%  [R_0402]  51.72 12.78 180 bottom
PR741  100K_0402_1%  [R_0402]  47.87 8.55 90 bottom
PR742  2_0402_5%  [R_0402]  41.56 15.14 180 bottom
PR743  10_1206_5%  [R_1206]  43.81 17.39 180 bottom
PR744  1M_0402_1%  [R_0402]  30.22 34.74 270 top
PR745  100_0402_1%  [R_0402]  49.89 15.23 0 bottom
PR746  1M_0402_1%  [R_0402]  29.2 40.52 270 top
PR749  200K_0402_1%  [R_0402]  41.6 14.41 180 top
PR750  200K_0402_1%  [R_0402]  41.6 13.26 180 top
PR751  76.8K_0402_1%  [R_0402]  44.77 14.41 180 top
PR752  127K_0402_1%  [R_0402]  44.77 13.26 180 top
PR753  182K_0402_1%  [R_0402]  41.4 7.66 90 bottom
PR754  499_0402_1%  [R_0402]  40.57 10.41 0 bottom
PR755  102K_0402_1%  [R_0402]  40.52 11.37 0 bottom
PR757  100K_0402_1%  [R_0402]  44.77 15.36 180 top
PR760  4.7_0402_5%  [R_0402]  45 17.77 0 bottom
PR762  4.02K_0402_1%  [R_0402]  27.87 39.6 90 top
PR763  4.02K_0402_1%  [R_0402]  28.44 33.85 270 top
PR764  10K_0402_1%  [R_0402]  40.54 13.21 0 bottom
PR765  0.01_1206_1%  [R_1206_4P]  29.07 22.01 180 bottom
PR766  4.7_1206_5%  [R_1206]  38.66 22.22 0 bottom
PR769  0_0402_5%  [R0402_0OHM]  46.98 8.55 90 bottom
PR770  0_0402_5%  [R0402_0OHM]  46.09 8.55 90 bottom
PR771  0_0603_5%  [R0603_0OHM]  48.44 18.09 90 bottom
PR772  0_0402_5%  [R0402_0OHM]  51.72 11.78 180 bottom
PR773  0_0603_5%  [R0603_0OHM]  24.19 25.14 0 top
PR774  0_0402_5%  [R0402_0OHM]  44.32 8.55 90 bottom
PR775  0_0402_5%  [R0402_0OHM]  43.43 8.55 90 bottom
PR776  0_0402_5%  [R0402_0OHM]  41.56 14.15 180 bottom
PR777  0_0402_5%  [R0402_0OHM]  45.21 8.55 90 bottom
PR779  0_0402_5%  [R0402_0OHM]  46.55 15.36 180 top
PR780  0_0603_5%  [R_0603]  38.65 11.94 180 top
PR801  10K_0402_1%  [R_0402]  71.88 48.3 90 bottom
PR802  10K_0402_5%  [R_0402]  75.61 46.98 0 bottom
PR803  0_0402_5%  [R0402_0OHM]  75.11 48.3 90 bottom
PR804  10K_0402_5%  [R_0402]  76 48.3 90 bottom
PR805  20K_0402_1%  [R_0402]  77.4 46.08 90 bottom
PR806  20K_0402_1%  [R_0402]  80.33 43.68 180 bottom
PR807  2K_0402_1%  [R_0402]  78.48 47.97 270 bottom
PR808  18K_0402_1%  [R_0402]  78.52 44.33 90 bottom
PR809  620K_0402_1%  [R_0402]  79.2 41.33 0 bottom
PR810  100_0402_1%  [R_0402]  80.1 39.54 180 bottom
PR811  0_0402_5%  [R0402_0OHM]  80.11 40.45 180 bottom
PR812  0_0402_5%  [R0402_0OHM]  75.56 38.59 90 bottom
PR813  100_0402_1%  [R_0402]  77.34 38.59 90 bottom
PR814  10K_0402_5%  [R_0402]  74.67 38.59 90 bottom
PR816  0_0603_5%  [R0603_0OHM]  73.32 39.78 180 bottom
PR817  0_0402_5%  [R0402_0OHM]  71.51 42.35 180 bottom
PR818  7.5K_0402_1%  [R_0402]  74.05 43.29 0 top
PR819  0_0603_5%  [R0603_0OHM]  73.57 46.12 180 bottom
PR821  4.7_1206_5%  [R_1206]  61.27 49.52 180 top
PR822  4.7_1206_5%  [R_1206]  61.27 43.23 180 top
PR823  0_0402_5%  [R0402_0OHM]  72.76 48.3 90 bottom
PR824  0_0402_5%  [R_0402]  78.51 46.16 0 bottom
PR825  1M_0402_1%  [R_0402]  73.65 48.3 90 bottom
PU100  -  [SY8286BRAC_QFN20_3X3]  62.92 13.71 90 bottom
PU102  -  [SY8286CRAC_QFN20_3X3]  63.81 25.45 90 bottom
PU200  -  [RT8207PGQW_WQFN20_3X3]  86.1 11.99 180 bottom
PU301  -  [SYX196DQNC_QFN10_3X3]  179.9 48.96 90 bottom
PU501  -  [SY8032ABC_SOT23-6]  83.88 27.67 0 bottom
PU602  ISL95859HRTZ-T_TQFN40_5X5  [ISL62883CHRTZ-T_TQFN40_5X5]  91.16 111.36 180 bottom
PU603  -  [AOZ5019QI_QFN23_5X3P5]  102.01 113.98 90 bottom
PU605  -  [AOZ5019QI_QFN23_5X3P5]  81.81 99.88 90 bottom
PU606  -  [ISL95808HRZ-TS2378_DFN8_2X2]  146.81 113.67 90 bottom
PU703  ISL95521HRZ-T_QFN32_4X4  [ISL95812HRZ-T_QFN32_4X4]  47.48 11.28 180 bottom
PU801  RT8812AGQW_WQFN20_3X3  [RT8207MZQW_WQFN20_3X3]  74.73 44.44 0 bottom
Q2407  MMBT3904WH_SOT323-3  [MMST3904-7-F_SOT323-3]  95.62 32.63 180 bottom
Q2408  MMBT3904WH_SOT323-3  [MMST3904-7-F_SOT323-3]  158.55 86.48 270 bottom
Q2409  -  [DMN66D0LDW-7_SOT363-6]  157.8 16.12 90 top
QC1  -  [2N7002K_SOT23-3]  149.54 69.49 180 top
QC2  -  [DMN66D0LDW-7_SOT363-6]  161.08 92.64 0 bottom
QC3  -  [DMN66D0LDW-7_SOT363-6]  161.17 96.07 180 bottom
QC4  -  [2N7002K_SOT23-3]  34.7 9.14 270 top
QE5  AP2606AGY-HF 1N SOT26-6  [SI3456BDV-T1-E3_TSOP6]  121.65 24.23 270 top
QE6  -  [DMN66D0LDW-7_SOT363-6]  25.27 64.68 90 bottom
QE7  2N7002KW 1N SOT323-3  [2N7002BKW_SOT323-3]  24.82 65.94 0 top
QE8  2N7002KW 1N SOT323-3  [2N7002BKW_SOT323-3]  24.82 68.99 0 top
QE9  -  [NTK3139PT1G_SOT723-3]  22.6 66.67 180 top
QE10  DDTA144VCA-7-F-GP  [2N7002K_SOT23-3]  90.73 53.95 0 top
QE11  -  [LN2306LT1G_SOT23-3]  94.32 53.55 315 top
QI1  -  [DMN66D0LDW-7_SOT363-6]  16.2 37.45 180 top
QI2  -  [DMN66D0LDW-7_SOT363-6]  16.2 41.84 180 top
QV2  -  [DMN65D8LDW-7_SOT363-6]  81.01 76.23 270 bottom
QV3  -  [2N7002E_SOT23-3]  76.45 71.96 180 top
QV4  2N7002KW 1N SOT323-3  [2N7002BKW_SOT323-3]  77.24 76.06 90 top
QV5  -  [DMN65D8LDW-7_SOT363-6]  90.25 69.92 45 top
QV6  DMG2301U-7 1P SOT23-3  [2N7002_SOT23-3]  92.77 69.04 180 top
QV7  -  [AON6552_DFN5X6-8-5]  97.46 73.52 270 top
QV8  -  [DMN65D8LDW-7_SOT363-6]  84.7 67.63 270 top
QV74  2N7002LT1G_SOT23-3  [2N7002K_SOT23-3]  88.04 74.01 135 top
QX3  -  [2N7002K_SOT23-3]  195.99 85.14 270 top
QX4  -  [DMN66D0LDW-7_SOT363-6]  195.4 77.84 180 top
QX5  -  [MMBT3904_NL_SOT23-3]  193.39 73.4 270 top
R2313  0_0402_5%  [R0402_0OHM]  172.14 10.14 90 top
R2318  0_0402_5%  [R0402_0OHM]  175.19 10.14 90 top
R2448  10K_0402_5%  [R_0402]  158.44 14.09 180 top
R2452  10K_0402_5%  [R_0402]  117.52 3.55 0 top
R2453  100K_0402_1%  [R_0402]  118.48 1.69 90 top
R2454  0_0402_5%  [R_0402]  134.49 22.74 270 top
R2455  0_0402_5%  [R_0402]  151.01 20.95 180 top
R2456  10K_0402_5%  [R_0402]  154.87 16.63 90 top
R2457  10K_0402_5%  [R_0402]  158.81 16.88 270 top
R2458  0_0402_5%  [R_0402]  157.35 15.04 180 top
R2459  0_0402_5%  [R_0402]  156.46 18.47 0 top
R2460  0_0402_5%  [R_0402]  153.03 21.89 180 top
RA4  200K_0402_5%  [R_0402]  192.33 19.66 90 top
RA8  0_0402_5%  [R0402_0OHM]  203.59 21.64 180 bottom
RA10  0_0402_5%  [R_0402]  188.58 21.01 0 bottom
RA11  0_0402_5%  [R_0402]  190.61 21.57 0 bottom
RA12  100K_0402_5%  [R_0402]  195.23 25.01 270 top
RA13  100K_0402_5%  [R_0402]  191.13 17.52 225 bottom
RA14  100K_0402_5%  [R_0402]  201.29 15.17 90 bottom
RA19  10K_0402_5%  [R_0402]  189.67 14.74 270 top
RA29  0_0402_1%  [R0402_0OHM]  196.21 35.03 90 top
RA30  0_0402_1%  [R0402_0OHM]  187.9 25.71 180 top
RA31  0_0402_1%  [R0402_0OHM]  201.43 24.25 180 top
RA32  0_0402_1%  [R0402_0OHM]  188.15 22.6 225 top
RA53  2.2K_0402_5%  [R_0402]  189.93 33.33 180 bottom
RA55  10_0402_1%  [R_0402]  196.86 24.74 90 bottom
RA56  10_0402_1%  [R_0402]  197.75 24.74 90 bottom
RA79  1K_0402_1%  [R_0402]  190.56 13.82 90 top
RA80  1K_0402_1%  [R_0402]  188.14 26.78 90 top
RA81  1K_0402_1%  [R_0402]  192.33 14.74 270 top
RA82  1K_0402_1%  [R_0402]  189.03 26.78 90 top
RA83  10K_0402_5%  [R_0402]  191.12 30.28 0 bottom
RA84  10K_0402_5%  [R_0402]  191.12 26.22 0 bottom
RA130  33_0402_5%  [R_0402]  195 13.69 90 bottom
RA165  4.7K_0402_5%  [R_0402]  189.03 30.1 270 bottom
RA166  4.7K_0402_5%  [R_0402]  189.35 26.27 90 bottom
RA1109  2.2K_0402_5%  [R_0402]  189.93 30.98 180 bottom
RA1110  0_0805_5%  [R0805_0OHM]  199.66 19.74 180 top
RA1111  0_0805_5%  [R0805_0OHM]  194.87 22.62 270 top
RA1112  0_0402_5%  [R_0402]  197.03 14.61 270 bottom
RA1113  0_0402_1%  [R0402_0OHM]  198.81 13.06 90 bottom
RA1114  0_0402_5%  [R_0402]  193.22 13.82 90 top
RA1115  0_0402_1%  [R0402_0OHM]  194.18 14.74 270 top
RC1  24.9_0402_1%  [R_0402]  122.7 97.97 90 top
RC2  1K_0402_5%  [R_0402]  116.26 107.64 270 bottom
RC3  1K_0402_5%  [R_0402]  110.48 108.14 270 bottom
RC4  499_0402_1%  [R_0402]  110.5 106.29 180 bottom
RC5  49.9_0402_1%  [R_0402]  143.06 74.43 270 top
RC6  49.9_0402_1%  [R_0402]  143.95 74.43 270 top
RC7  49.9_0402_1%  [R_0402]  113.2 97.93 90 top
RC8  49.9_0402_1%  [R_0402]  115.31 97.9 90 top
RC9  1K_0402_5%  [R_0402]  159.14 77.14 180 bottom
RC10  1K_0402_5%  [R_0402]  156.06 88.57 0 bottom
RC11  51_0402_5%  [R_0402]  119.44 106.72 90 bottom
RC12  0_0402_5%  [R0402_0OHM]  155.75 101.72 0 top
RC13  51_0402_5%  [R_0402]  119.44 109.01 90 bottom
RC14  49.9_0402_1%  [R_0402]  117.47 109.01 90 bottom
RC15  51_0402_5%  [R_0402]  121.15 109.01 90 bottom
RC16  1K_0402_5%  [R_0402]  151.17 89.84 0 top
RC17  1K_0402_5%  [R_0402]  144.96 70.3 270 top
RC21  1K_0402_5%  [R_0402]  155.87 78.92 0 bottom
RC31  1K_0402_5%  [R_0402]  153.66 107.13 270 bottom
RC35  51_0402_1%  [R_0402]  117.47 106.72 90 bottom
RC37  51_0402_5%  [R_0402]  121.15 106.79 90 bottom
RC38  121_0402_1%  [R_0402]  140.39 74.43 270 top
RC39  80.6_0402_1%  [R_0402]  141.28 74.43 270 top
RC40  100_0402_1%  [R_0402]  142.17 74.43 270 top
RC43  0_0402_5%  [R_0402]  107.37 107.1 90 bottom
RC44  1K_0402_5%  [R_0402]  155.87 78.03 0 bottom
RC45  22_0402_5%  [R_0402]  160.27 70.17 270 top
RC46  0_0402_5%  [R_0402]  158.22 78.03 0 bottom
RC47  1K_0402_1%  [R_0402]  158.22 79.81 0 bottom
RC48  1K_0402_1%  [R_0402]  156.19 82.22 0 bottom
RC49  499_0402_1%  [R_0402]  156.06 94.1 0 bottom
RC50  499_0402_1%  [R_0402]  156.06 94.99 0 bottom
RC51  1K_0402_1%  [R_0402]  156.19 81.33 0 bottom
RC52  33_0402_5%  [R_0402]  158.22 78.92 0 bottom
RC53  4.7K_0402_5%  [R_0402]  156.19 83.11 0 bottom
RC54  22_0402_5%  [R_0402]  159.38 70.17 270 top
RC55  0_0402_5%  [R_0402]  157.98 66.53 90 top
RC56  0_0402_5%  [R_0402]  159.84 63.94 270 top
RC57  33_0402_5%  [R_0402]  155.87 79.94 0 bottom
RC58  33_0402_5%  [R_0402]  155.87 77.14 0 bottom
RC59  33_0402_5%  [R_0402]  158.22 80.7 0 bottom
RC60  33_0402_5%  [R_0402]  155.31 81.86 270 bottom
RC61  15_0402_1%  [R_0402]  183.51 26.04 270 top
RC62  49.9K_0402_1%  [R_0402]  159.2 90.28 0 bottom
RC63  49.9K_0402_1%  [R_0402]  159.2 89.4 0 bottom
RC64  10K_0402_5%  [R_0402]  155.94 89.93 0 bottom
RC65  49.9K_0402_1%  [R_0402]  161.4 86.22 0 bottom
RC66  0_0402_5%  [R_0402]  155.34 70.24 270 top
RC67  49.9K_0402_1%  [R_0402]  170.48 49.65 0 top
RC68  49.9K_0402_1%  [R_0402]  158.3 90.3 270 bottom
RC76  200_0402_1%  [R_0402]  147.71 92.57 0 top
RC78  100K_0402_5%  [R_0402]  28.37 59.53 90 bottom
RC80  100_0402_1%  [R_0402]  145.79 100.8 180 top
RC89  200_0402_1%  [R_0402]  155.26 83.18 180 bottom
RC91  20K_0402_5%  [R_0402]  146.74 70.34 90 top
RC92  1M_0402_5%  [R_0402]  133.34 106.77 180 bottom
RC93  20K_0402_5%  [R_0402]  148.32 72.19 0 top
RC94  1M_0402_5%  [R_0402]  147.88 71.25 270 top
RC95  1M_0402_5%  [R_0402]  153.16 66.4 90 top
RC96  2.7K_0402_1%  [R_0402]  126.87 100.46 270 top
RC98  10M_0402_5%  [R_0402]  154.3 84.88 90 bottom
RC99  100K_0402_5%  [R_0402]  166.69 63.94 180 top
RC101  100K_0402_5%  [R_0402]  154.06 65.52 180 top
RC102  1K_0402_5%  [R_0402]  106.72 102.42 0 bottom
RC103  8.2K_0402_5%  [R_0402]  152.27 71.61 90 top
RC104  1K_0402_5%  [R_0402]  154.43 69.32 90 top
RC105  1K_0402_5%  [R_0402]  158.87 67.44 270 top
RC106  10K_0402_5%  [R_0402]  152.27 70.24 270 top
RC107  8.2K_0402_5%  [R_0402]  156.64 70.15 270 top
RC108  10K_0402_5%  [R_0402]  159.95 60.14 270 top
RC109  0_0402_5%  [R0402_0OHM]  160.71 67.44 270 top
RC110  8.2K_0402_5%  [R_0402]  151.19 74.3 270 top
RC111  100K_0402_5%  [R_0402]  152.27 66.4 90 top
RC112  0_0402_5%  [R_0402]  154.98 65.4 0 top
RC113  1K_0402_5%  [R_0402]  112.83 109.92 270 bottom
RC115  10K_0402_5%  [R_0402]  150.3 73.38 90 top
RC116  60.4_0402_1%  [R_0402]  112.83 107.64 270 bottom
RC117  2.2K_0402_5%  [R_0402]  159.82 73.38 90 top
RC118  4.7K_0402_5%  [R_0402]  157.16 73.38 90 top
RC119  113_0402_1%  [R_0402]  149.46 92.57 0 top
RC120  100_0402_1%  [R_0402]  149.66 100.27 270 top
RC121  10K_0402_5%  [R_0402]  146.95 68.83 180 top
RC122  10K_0402_5%  [R_0402]  157.59 70.15 270 top
RC123  100K_0402_5%  [R_0402]  160.79 57.46 180 top
RC124  60.4_0402_1%  [R_0402]  127.82 100.44 90 top
RC125  10K_0402_5%  [R_0402]  158.93 73.38 90 top
RC126  10K_0402_5%  [R_0402]  156.27 73.38 90 top
RC127  10K_0402_5%  [R_0402]  152.27 73.38 90 top
RC128  0_0402_5%  [R0402_0OHM]  155.19 63.63 270 top
RC129  100K_0402_5%  [R_0402]  160.79 56.57 180 top
RC130  10K_0402_5%  [R_0402]  130.42 22.33 90 top
RC140  0_0402_5%  [R0402_0OHM]  140.95 102.23 0 top
RC141  0_0402_5%  [R0402_0OHM]  137 86.7 0 top
RC143  0_0402_5%  [R0402_0OHM]  140.09 102.23 180 top
RC144  0_0402_5%  [R_0402]  159.76 67.44 270 top
RC148  0_0603_5%  [R0603_0OHM]  154.62 101.65 270 top
RC152  0_0603_5%  [R0603_0OHM]  148.06 100.37 180 top
RC154  0_0402_5%  [R0402_0OHM]  150.3 72.08 270 top
RC161  0_0402_5%  [R0402_0OHM]  145.86 88.73 180 top
RC162  0_0402_5%  [R0402_0OHM]  151.81 95.18 0 top
RC163  0_0402_5%  [R0402_0OHM]  156.28 94.1 180 top
RC166  10K_0402_5%  [R_0402]  178.49 94.59 90 top
RC167  0_0402_5%  [R0402_0OHM]  158.48 94.1 0 bottom
RC169  0_0603_5%  [R0603_0OHM]  151.63 101.91 180 top
RC171  0_0402_5%  [R0402_0OHM]  149.47 88.59 270 top
RC172  0_0402_5%  [R0402_0OHM]  144.77 90.22 45 top
RC174  0_0402_5%  [R_0402]  177.54 98.24 270 top
RC177  0_0402_5%  [R_0402]  164.41 56.57 180 top
RC178  0_0402_5%  [R0402_0OHM]  161.72 56.57 0 top
RC179  56_0402_5%  [R_0402]  115.25 109.92 270 bottom
RC180  220_0402_5%  [R_0402]  114.99 106.72 90 bottom
RC181  100_0402_1%  [R_0402]  114.36 109.92 270 bottom
RC182  0_0402_5%  [R0402_0OHM]  165.78 63.05 0 top
RC183  0_0402_5%  [R0402_0OHM]  110.09 84.45 0 top
RC184  100K_0402_5%  [R_0402]  113.91 106.72 90 bottom
RC185  49.9_0402_1%  [R_0402]  117.97 100.8 180 top
RC188  0_0402_5%  [R0402_0OHM]  165.28 42.23 270 top
RC190  0_0603_5%  [R0603_0OHM]  153.41 101.65 270 top
RC191  0_0402_5%  [R_0402]  176.59 98.24 270 top
RC192  1K_0402_5%  [R_0402]  32.06 9.53 270 top
RC193  1K_0402_1%  [R_0402]  107.64 101.34 180 bottom
RC194  0_0402_5%  [R0402_0OHM]  178.62 72.75 90 top
RC195  0_0402_5%  [R0402_0OHM]  160.9 60.14 270 top
RC196  0_0402_5%  [R_0402]  151.25 88.59 270 top
RC197  0_0402_5%  [R0402_0OHM]  150.36 88.59 270 top
RC199  10K_0402_5%  [R_0402]  155.62 104.89 0 bottom
RC200  10K_0402_5%  [R_0402]  155.62 104 0 bottom
RC201  10K_0402_5%  [R_0402]  158.3 71.61 90 top
RC202  4.7K_0402_5%  [R_0402]  158.48 94.99 0 bottom
RC203  100_0402_1%  [R_0402]  135.11 100.83 0 top
RC204  0_0402_5%  [R_0402]  166.69 61.08 180 top
RC205  100_0402_1%  [R_0402]  135.01 101.69 180 top
RC206  10K_0402_5%  [R_0402]  157.85 106.28 90 bottom
RC208  0_0603_5%  [R0603_0OHM]  130.22 86.96 180 top
RC209  0_0603_5%  [R0603_0OHM]  30.51 13.44 180 top
RC210  0_0402_5%  [R_0402]  188.78 74.02 90 top
RC211  10K_0402_5%  [R_0402]  154.81 97.58 90 bottom
RC214  10K_0402_5%  [R_0402]  155.71 99.37 180 bottom
RC215  10K_0402_5%  [R_0402]  155.58 108 180 bottom
RC216  10K_0402_5%  [R_0402]  160.71 73.38 90 top
RC217  10K_0402_5%  [R_0402]  152.71 107.13 270 bottom
RC218  10K_0402_5%  [R_0402]  144.96 67.61 90 top
RC219  100_0402_1%  [R_0402]  107.5 96.88 90 bottom
RC220  100K_0402_5%  [R_0402]  147.52 93.46 180 top
RC221  4.7K_0402_5%  [R_0402]  151.19 72.08 270 top
RC222  10K_0402_5%  [R_0402]  156.28 95.88 180 top
RC223  100K_0402_5%  [R_0402]  146.84 95.5 180 top
RC224  10K_0402_5%  [R_0402]  155.57 107.13 270 bottom
RC225  10K_0402_5%  [R_0402]  165.42 58.54 180 top
RC226  100_0402_1%  [R_0402]  107.5 96.02 270 bottom
RC227  100_0402_1%  [R_0402]  139.18 99.55 180 top
RC228  100_0402_1%  [R_0402]  140.3 100.7 0 top
RC229  10K_0402_5%  [R_0402]  156.28 93.21 180 top
RC230  10K_0402_5%  [R_0402]  157.52 99.37 0 bottom
RC231  10K_0402_5%  [R_0402]  155.68 103.05 0 bottom
RC232  10K_0402_5%  [R_0402]  156.6 102.16 180 bottom
RC233  10K_0402_5%  [R_0402]  156.58 99.36 90 bottom
RC234  10K_0402_5%  [R_0402]  157.23 96.96 180 top
RC312  100K_0402_5%  [R_0402]  148.91 95.18 180 top
RC314  10K_0402_5%  [R_0402]  166.95 95.24 180 bottom
RC315  10K_0402_5%  [R_0402]  164.53 94.35 180 bottom
RC316  10K_0402_5%  [R_0402]  164.53 93.08 180 bottom
RC317  10K_0402_5%  [R_0402]  164.53 91.18 180 bottom
RC318  10K_0402_5%  [R_0402]  166.95 94.35 180 bottom
RC319  10K_0402_5%  [R_0402]  164.53 95.24 180 bottom
RC320  10K_0402_5%  [R_0402]  166.03 91.24 0 bottom
RC321  10K_0402_5%  [R_0402]  166.03 93.08 0 bottom
RC322  10K_0402_5%  [R_0402]  156.06 92.26 0 bottom
RC323  10K_0402_5%  [R_0402]  166.95 92.19 180 bottom
RC324  10K_0402_5%  [R_0402]  156.06 93.15 0 bottom
RC325  10K_0402_5%  [R_0402]  159.39 93.15 180 bottom
RC326  10K_0402_5%  [R_0402]  164.53 92.19 180 bottom
RC327  10K_0402_5%  [R_0402]  160.78 63.31 270 top
RC329  10K_0402_5%  [R_0402]  161.85 60.14 270 top
RC330  10K_0402_5%  [R_0402]  155.37 94.99 0 top
RC345  0_0402_5%  [R0402_0OHM]  109.35 99.62 180 top
RC361  0_0402_5%  [R_0402]  147.13 91.62 135 top
RC388  1K_0402_5%  [R_0402]  109.35 101.4 180 top
RC389  0_0402_5%  [R_0402]  108.44 100.51 0 top
RC390  1K_0402_5%  [R_0402]  161.93 94.03 180 bottom
RC391  1K_0402_5%  [R_0402]  161.21 89.65 0 bottom
RC392  0_0402_5%  [R0402_0OHM]  108.44 98.73 0 top
RC393  0_0603_5%  [R0603_0OHM]  180.59 72.83 90 top
RC394  1K_0402_5%  [R_0402]  158.48 91.37 0 bottom
RC395  1K_0402_5%  [R_0402]  158.48 92.26 0 bottom
RC396  0_0402_5%  [R_0402]  154.17 62.72 90 top
RC397  0_0402_5%  [R_0402]  162.17 96.12 90 bottom
RC398  0_0402_5%  [R_0402]  163.65 58.54 180 top
RC399  0_0402_5%  [R_0402]  158.87 97.03 270 bottom
RC400  10M_0402_5%  [R_0402]  32.95 8.61 90 top
RC402  0_0402_5%  [R_0402]  154.68 107.13 270 bottom
RD1  470_0402_5%  [R_0402]  106.8 33.7 90 top
RD8  0_0402_5%  [R0402_0OHM]  138.3 37.51 90 top
RD9  1.8K_0402_1%  [R_0402]  98.62 48.12 180 top
RD10  2_0402_1%  [R_0402]  97.71 49.01 0 top
RD11  1.8K_0402_1%  [R_0402]  97.78 49.95 90 top
RD12  24.9_0402_1%  [R_0402]  98.69 51.74 180 top
RD13  1.8K_0402_1%  [R_0402]  108.72 33.65 180 top
RD14  2_0402_1%  [R_0402]  107.8 34.54 0 top
RD15  1.8K_0402_1%  [R_0402]  107.8 35.49 0 top
RD16  24.9_0402_1%  [R_0402]  110.56 35.49 180 top
RD17  0_0402_5%  [R0402_0OHM]  150.23 25.82 90 top
RD18  1.8K_0402_1%  [R_0402]  150.23 29.4 270 top
RD19  2_0402_1%  [R_0402]  151.56 26.74 270 top
RD20  1.8K_0402_1%  [R_0402]  150.25 27.61 180 top
RD21  24.9_0402_1%  [R_0402]  151.12 27.6 90 top
RE50  10K_0402_5%  [R_0402]  2.52 73.97 0 top
RE58  100K_0402_5%  [R_0402]  124.59 17.96 180 top
RE61  51K_0402_5%  [R_0402]  124.59 17.07 180 top
RE329  10K_0402_5%  [R_0402]  24.05 63.05 0 top
RE330  100K_0402_5%  [R_0402]  94.61 57.21 225 top
RE332  7.15K_0402_1%  [R_0402]  152.95 18.34 0 top
RE333  10K_0402_1%  [R_0402]  152.95 19.23 0 top
RE334  4.7K_0402_5%  [R_0402]  25.58 62.72 90 bottom
RE335  4.7K_0402_5%  [R_0402]  26.85 62.72 90 bottom
RE336  0_0402_5%  [R_0402]  27.74 62.72 90 bottom
RE337  0_0402_5%  [R_0402]  24.69 62.72 90 bottom
RE338  4.7K_0402_5%  [R_0402]  20.44 66.55 270 top
RE339  4.7K_0402_5%  [R_0402]  21.33 66.55 270 top
RE342  0_0603_5%  [R0603_0OHM]  151.95 15.23 0 top
RE343  27K_0402_1%  [R_0402]  116.59 3.55 180 top
RE344  100K_0402_1%  [R_0402]  115.69 1.69 90 top
RE345  0_0603_5%  [R0603_0OHM]  153.41 3.33 0 top
RE346  0_0402_5%  [R0402_0OHM]  137.22 21.82 90 top
RE347  4.7K_0402_5%  [R_0402]  149.46 8.06 0 top
RE348  100K_0402_5%  [R_0402]  128.15 19.42 180 top
RE349  4.7K_0402_5%  [R_0402]  149.46 8.94 0 top
RE350  2.2K_0402_5%  [R_0402]  149.46 9.83 0 top
RE351  2.2K_0402_5%  [R_0402]  149.46 10.72 0 top
RE352  10K_0402_5%  [R_0402]  148.52 6.74 270 top
